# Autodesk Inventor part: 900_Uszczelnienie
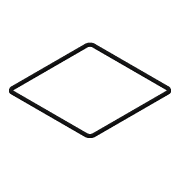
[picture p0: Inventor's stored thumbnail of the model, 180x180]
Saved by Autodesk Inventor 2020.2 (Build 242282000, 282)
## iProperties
Created: 2006-01
Part Number: 900_Uszczelnienie
Document SubType Name: Modeling
Designer: F.Stasiak
Density: 1 g/cm^3
Material: Ogólny
Appearance: Czarny winyl (tekstura)
Manager: www.cadconsulting.pl
Company: Fabian Stasiak CAD Consulting
Author: F.Stasiak
Subject: Zbiór ćwiczeń. Autodesk Inventor 2020. Kurs podstawowy
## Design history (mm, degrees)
sketch "Szkic1"
  geometry: L1 (-170, -160)-(-170, 160) reference; L2 (-160, 170)-(160, 170) reference; L3 (160, -170)-(-160, -170) reference; L4 (170, 160)-(170, -160) reference; L5 (-182, 160)-(-182, -160); L6 (-160, -182)-(160, -182); L7 (182, -160)-(182, 160); L8 (160, 182)-(-160, 182); A1 r 10 centre (-160, 160) between (-160, 170) and (-170, 160) reference; A2 r 10 centre (160, 160) between (170, 160) and (160, 170) reference; A3 r 10 centre (160, -160) between (160, -170) and (170, -160) reference; A4 r 10 centre (-160, -160) between (-170, -160) and (-160, -170) reference; A5 r 22 centre (-160, -160) between (-182, -160) and (-160, -182); A6 r 22 centre (160, -160) between (160, -182) and (182, -160); A7 r 22 centre (160, 160) between (182, 160) and (160, 182); A8 r 22 centre (-160, 160) between (-160, 182) and (-182, 160)
  constraints: 8 end point, 8 point on circle, 4 centre point, 7 other
  dimensions: "d0" = 12 distance between parallel lines of L7 L4
extrude "Wyciągnięcie proste1" new body sketch "Szkic1" distance "d1" = 10; taper "d2" = 0 deg
fillet "Zaokrąglenie1" dims "d3" = 5
node "Bryła1"
node "Korpusy bryłowe"
node "Korpusy powierzchniowe"
node "Odniesienie1"
node "Odniesienie2"
node "Odniesienie3"
node "Odniesienie4"
node "Odniesienie5"
node "Odniesienie6"
node "Odniesienie7"
node "Odniesienie8"
